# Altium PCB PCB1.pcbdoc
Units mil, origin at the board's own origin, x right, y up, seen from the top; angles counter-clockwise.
Board outline 2204.33 x 2174.33 mil, 4 copper layers (Top Layer, Inner1, Inner2, Bottom Layer); 61 components, 57 nets, 255 pads, 99 vias.
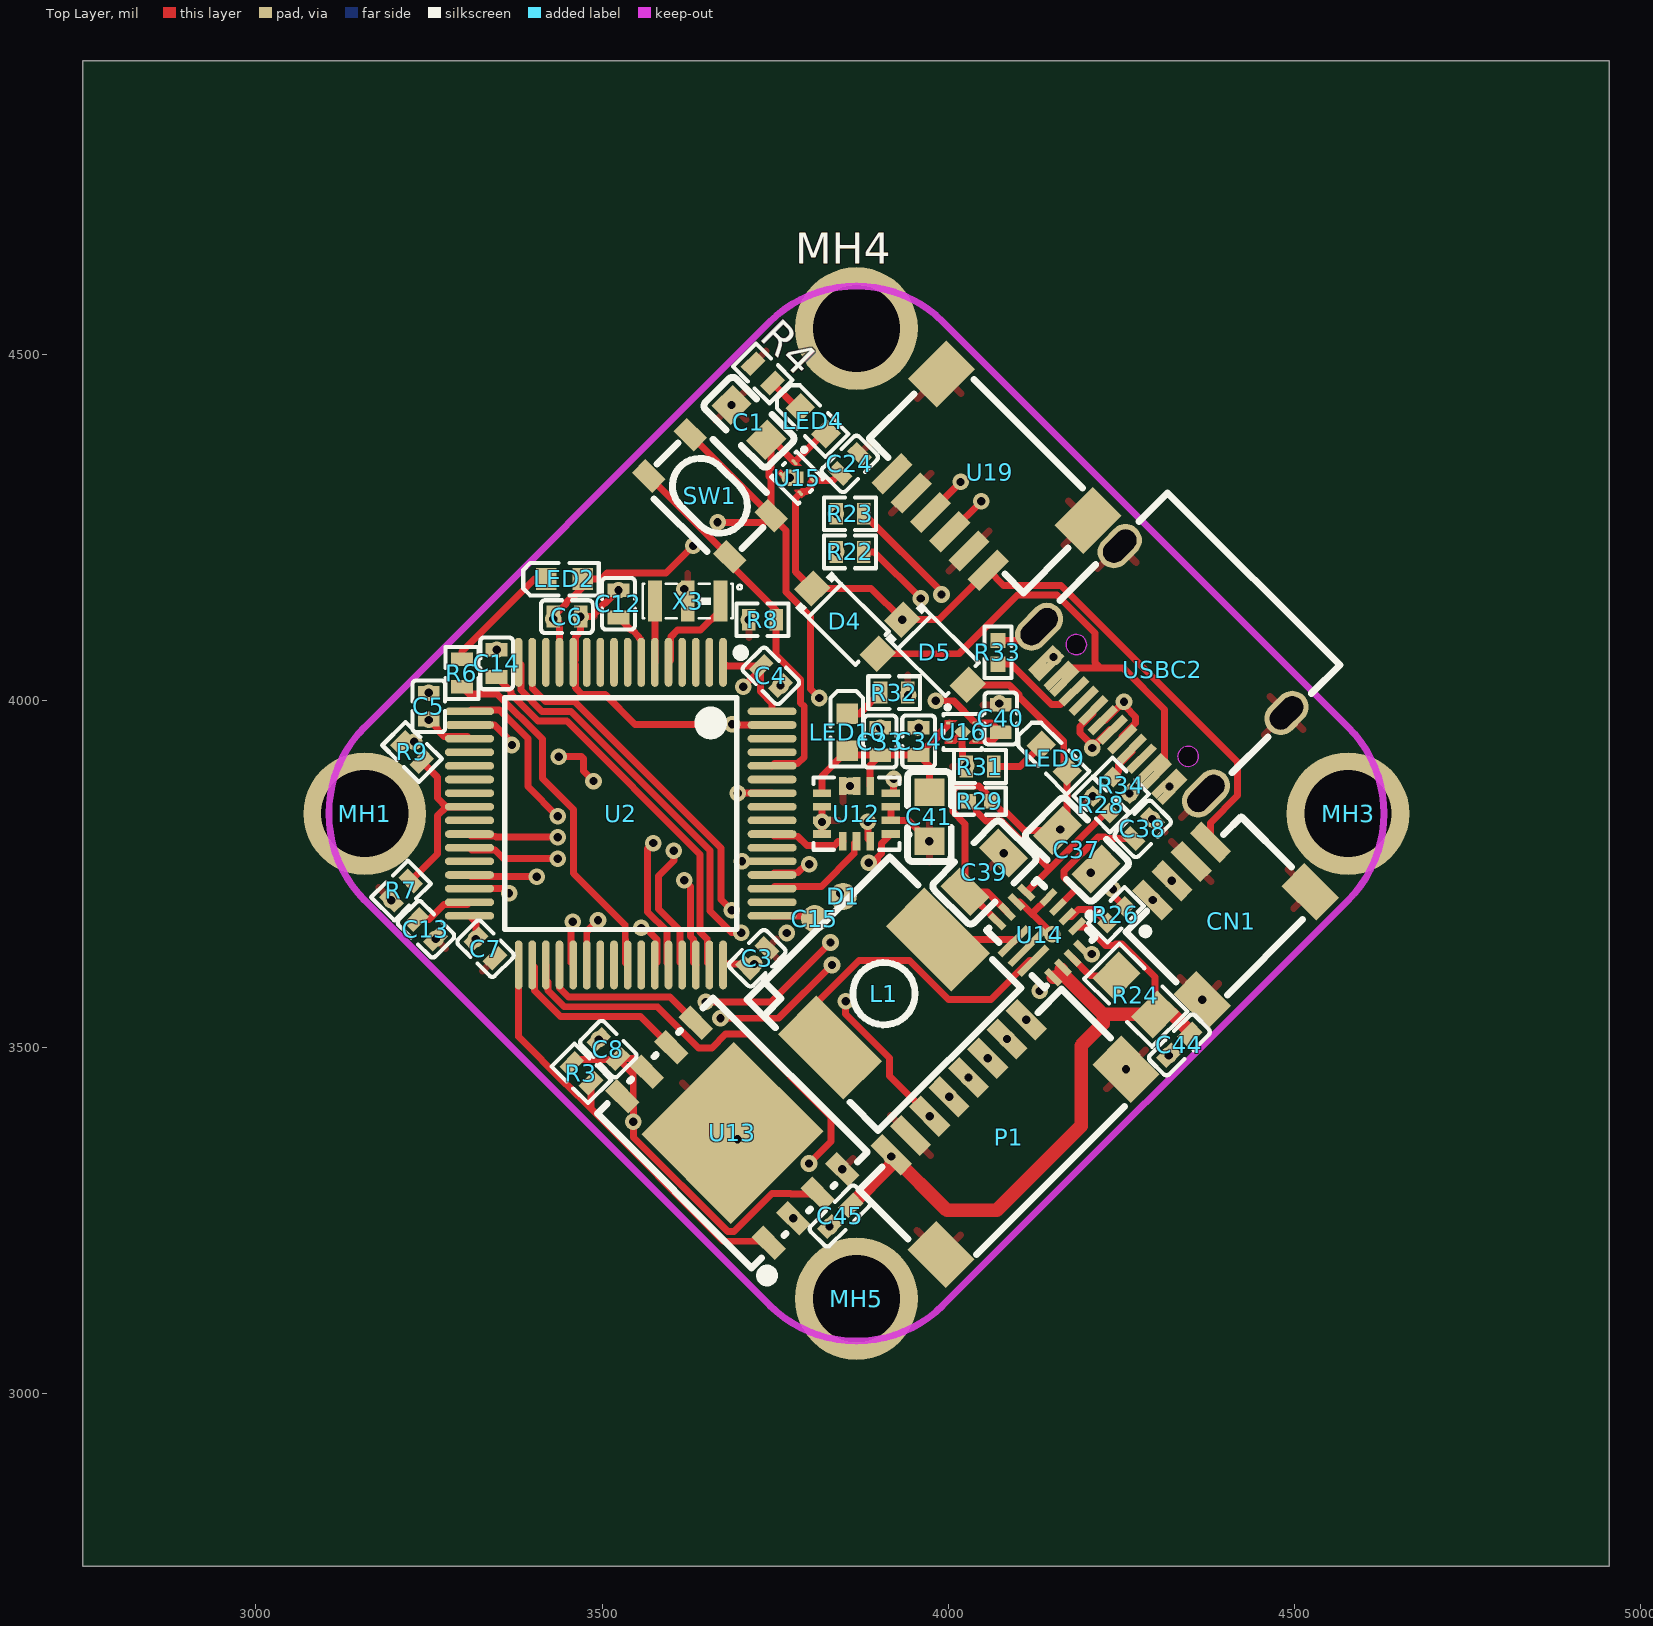
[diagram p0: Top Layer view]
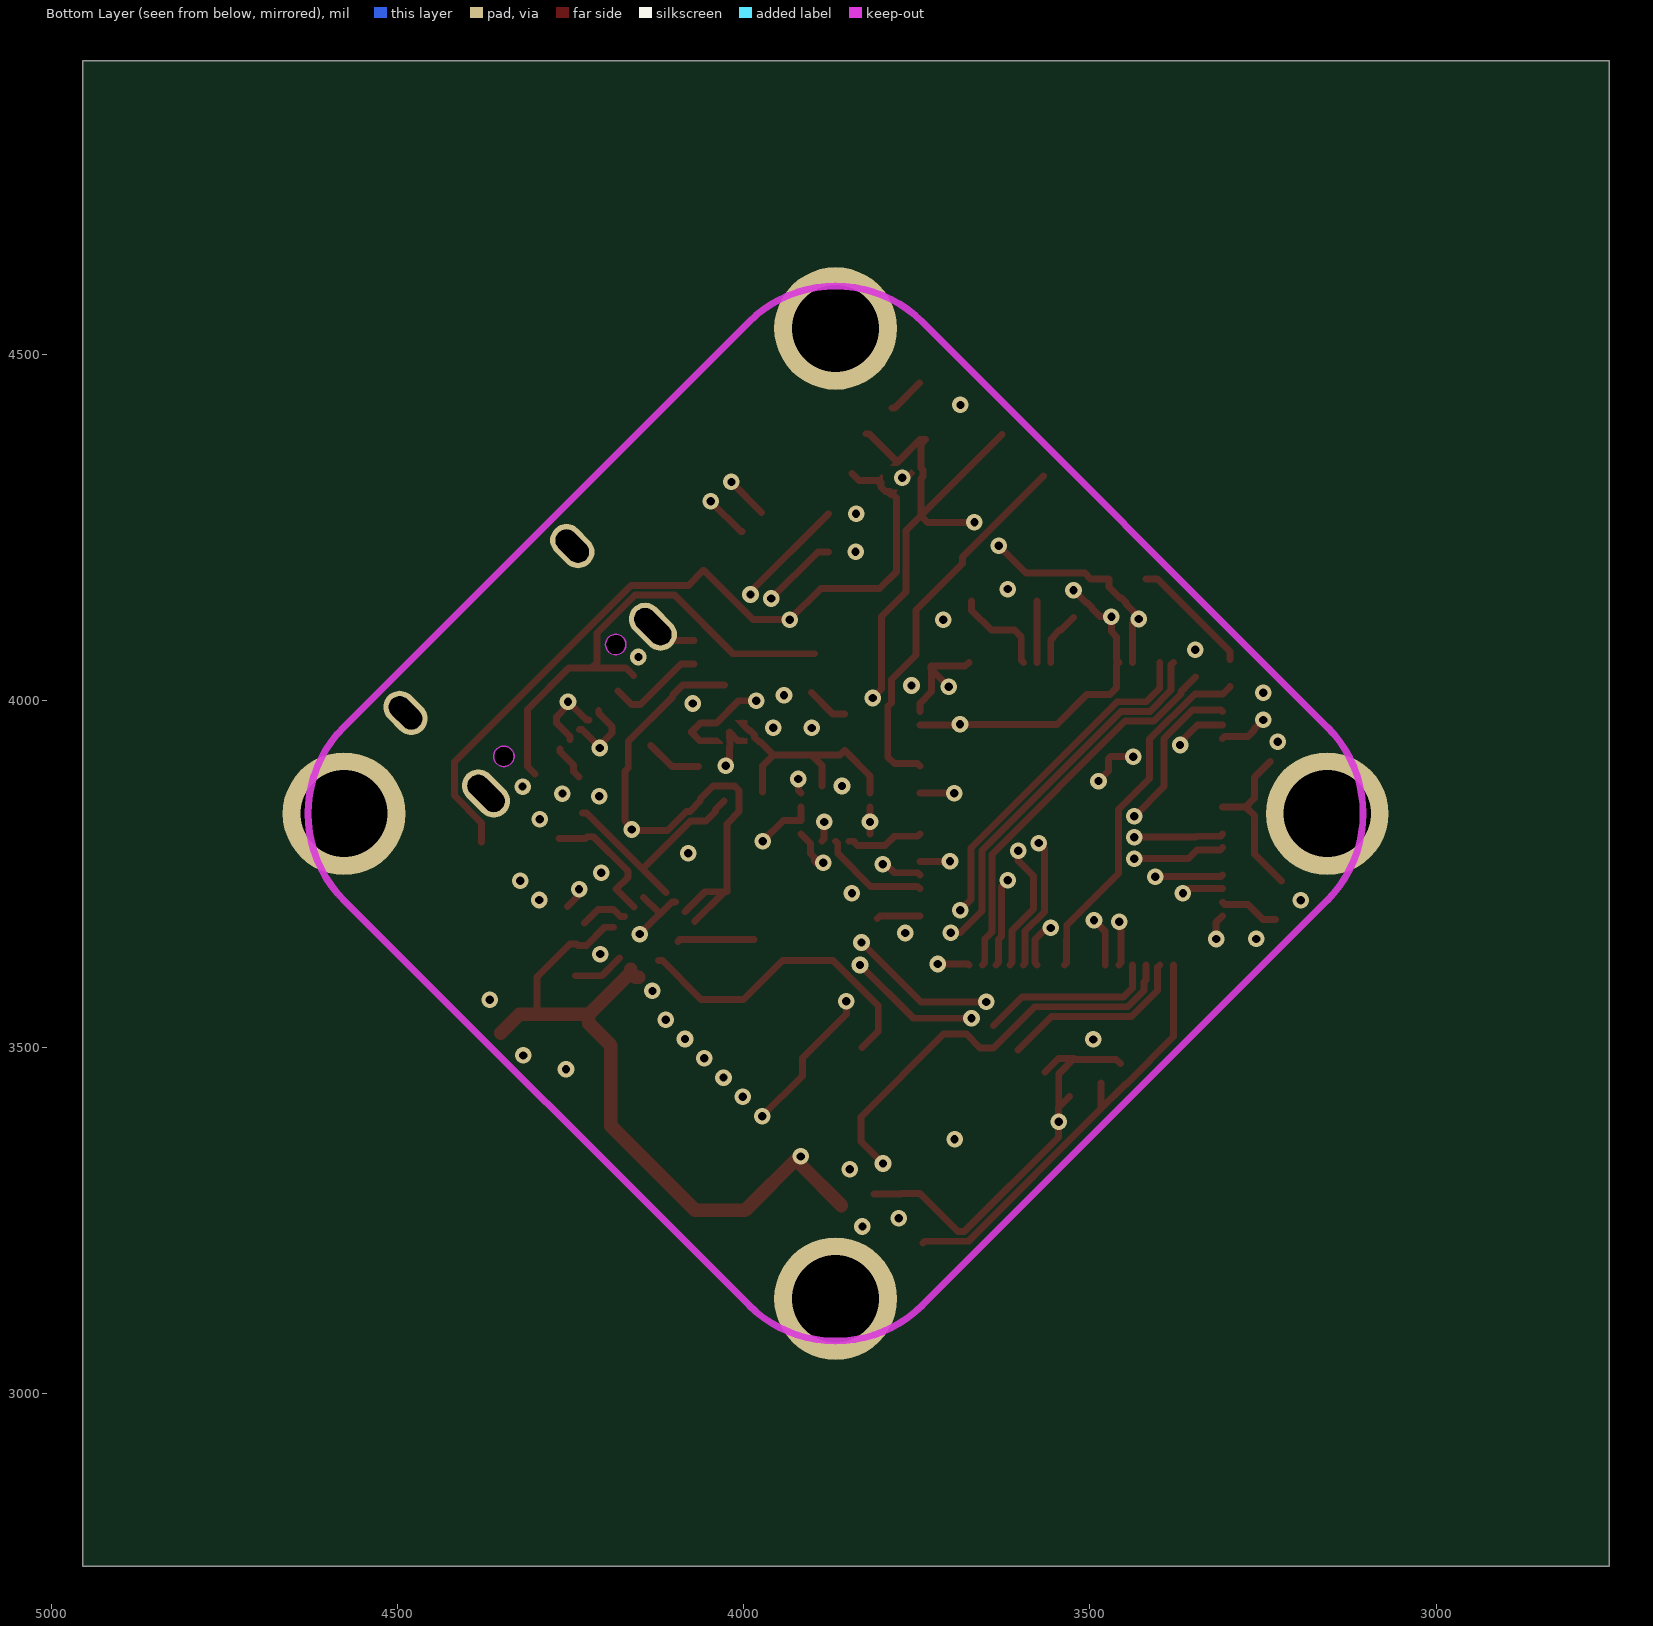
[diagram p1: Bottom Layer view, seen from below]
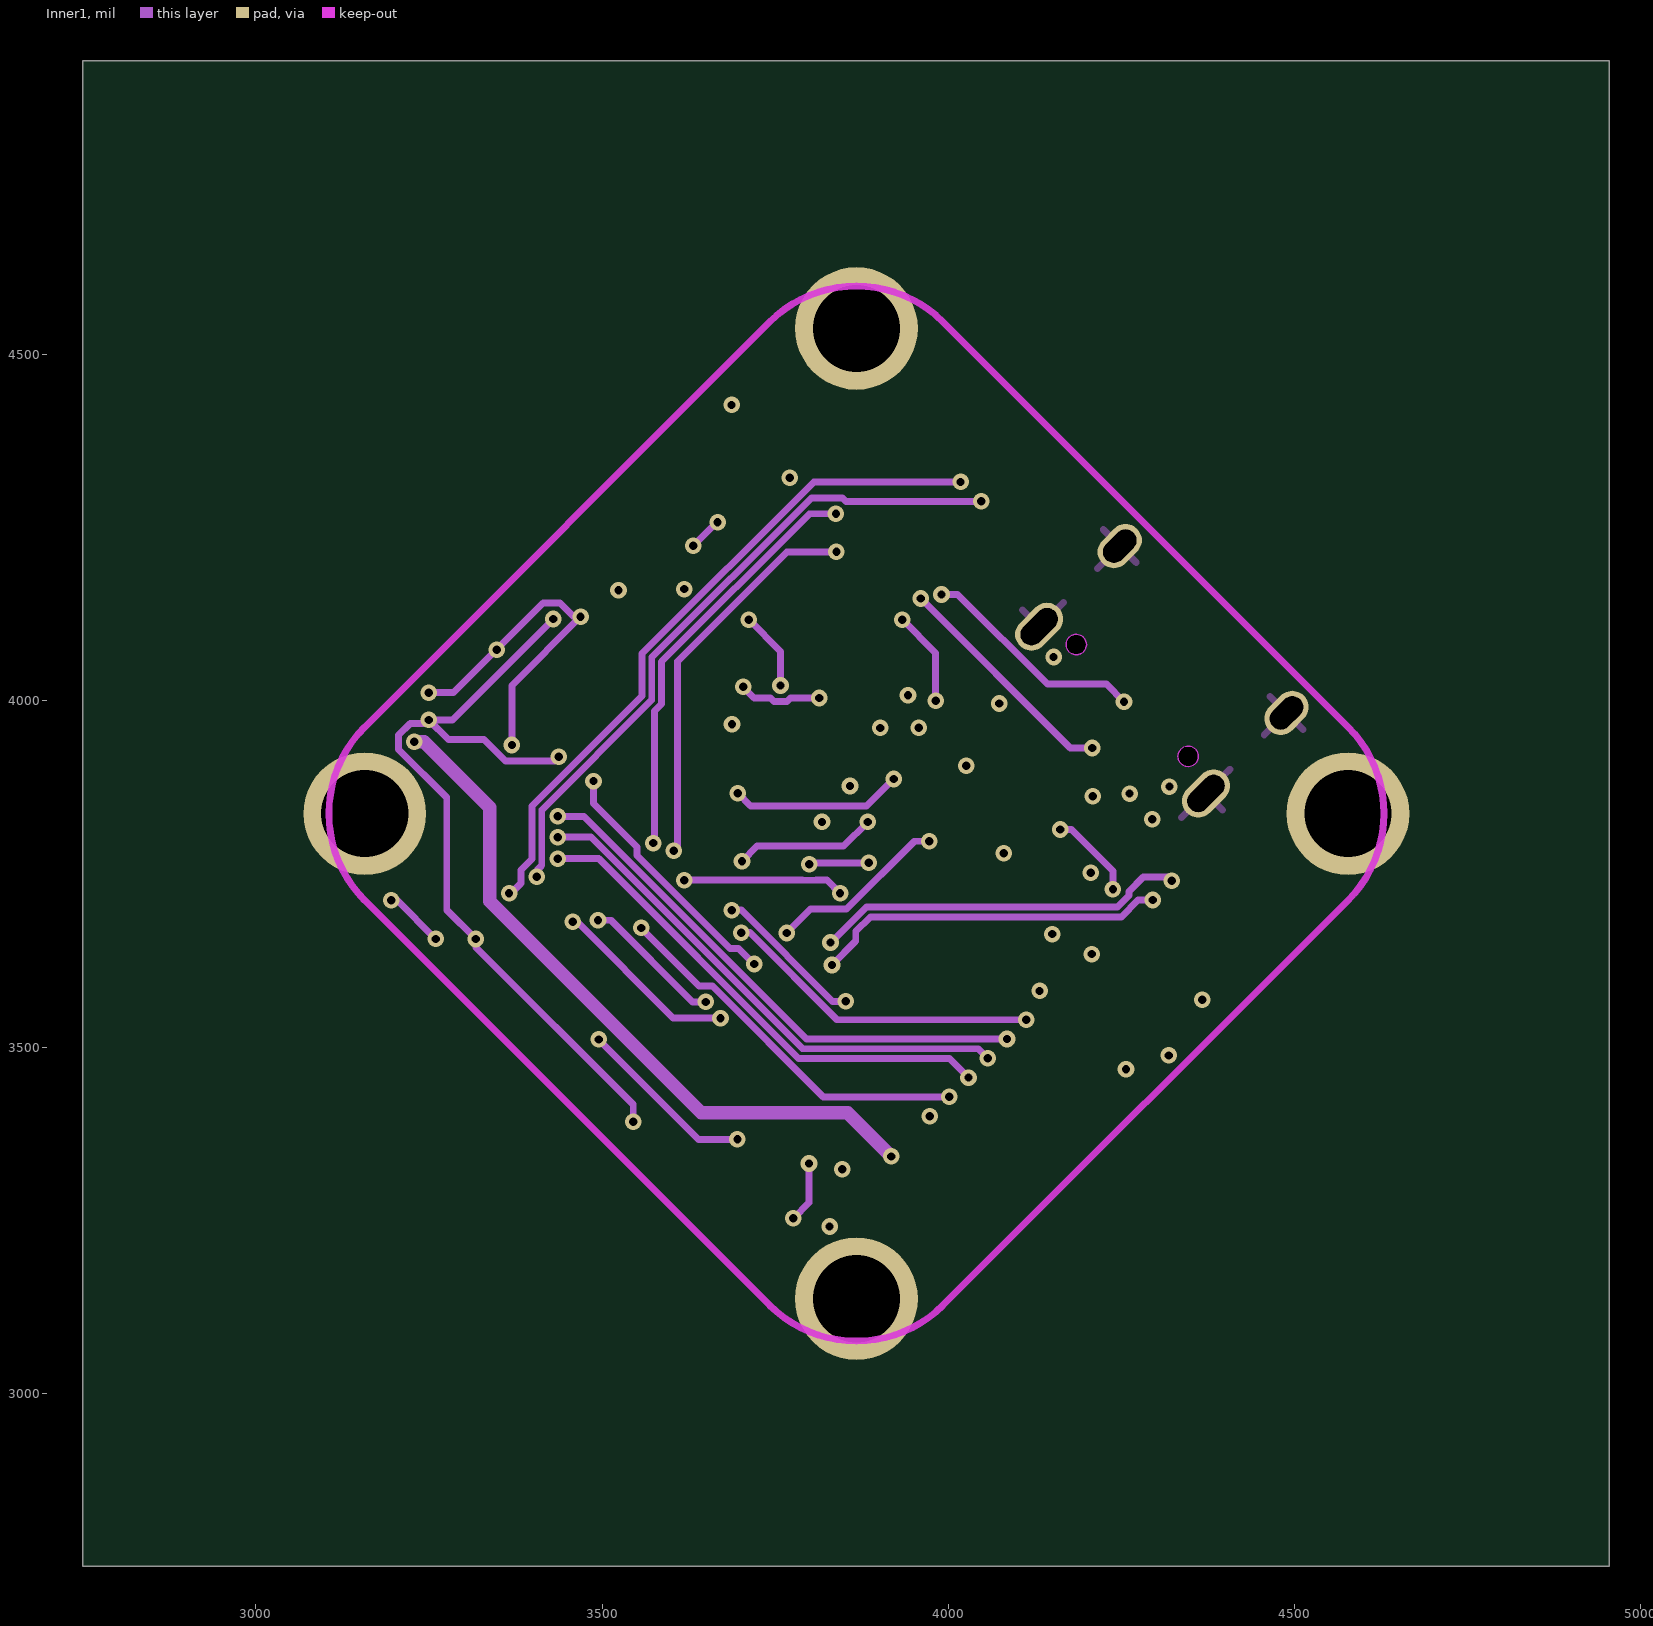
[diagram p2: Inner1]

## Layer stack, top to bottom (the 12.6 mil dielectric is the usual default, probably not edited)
Top Layer: signal copper (thickness not stored)
Dielectric: dielectric 12.6, FR-4, Dk 4.8
Inner1: signal copper (thickness not stored)
Dielectric: dielectric 12.6, FR-4, Dk 4.8
Inner2: signal copper (thickness not stored)
Dielectric: dielectric 12.6, FR-4, Dk 4.8
Bottom Layer: signal copper (thickness not stored)

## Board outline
4954.33,2750 2750,2750 2750,4924.33 4954.33,4924.33

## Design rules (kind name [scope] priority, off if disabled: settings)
BoardOutlineClearance copperThickness1oz [All] p0: genericclearance=10 ignorepadtopadclearanceinfootprint=FALSE except(0: Arc-SplitContinuation Track-SplitContinuation SMDPad-SplitContinuation THPad-SplitContinuation Via-SplitContinuation Fill-SplitContinuation Poly-SplitContinuation Region-SplitContinuation Text-SplitContinuation; 6: Track-CutoutEdge SMDPad-CutoutEdge THPad-CutoutEdge Via-CutoutEdge Region-CutoutEdge; 11.8: Track-OutlineEdge SMDPad-OutlineEdge THPad-OutlineEdge Via-OutlineEdge Fill-OutlineEdge Region-OutlineEdge Poly-OutlineEdge Text-OutlineEdge Fill-CutoutEdge)
BoardOutlineClearance copperThickness2oz [All] p0: genericclearance=10 ignorepadtopadclearanceinfootprint=FALSE except(0: Arc-SplitContinuation Track-SplitContinuation SMDPad-SplitContinuation THPad-SplitContinuation Via-SplitContinuation Fill-SplitContinuation Poly-SplitContinuation Region-SplitContinuation Text-SplitContinuation; 6: Track-CutoutEdge SMDPad-CutoutEdge THPad-CutoutEdge Via-CutoutEdge Region-CutoutEdge; 11.8: Track-OutlineEdge SMDPad-OutlineEdge THPad-OutlineEdge Via-OutlineEdge Fill-OutlineEdge Region-OutlineEdge Poly-OutlineEdge Text-OutlineEdge Fill-CutoutEdge)
Clearance copperThickness1oz [(InNet('GND') OR InNet('3V3') OR InNet('$1N1828') OR InNet('$1N1826') OR InNet('$1N1817') OR InNet('$1N1793') OR InNet('5V') OR InNet('5V_REG') OR InNet('3V3_MPU') OR InNet('$1N6590') OR InNet('RX6') OR InNet('TX6') OR InNet('$1N1792') OR InNet('5V_USB') OR InNet('$1N5670') OR InNet('$1N5674') OR InNet('$1N1796') OR InNet('$1N3338') OR InNet('$1N6799') OR InNet('$1N9049') OR InNet('ADC_CURR') OR InNet('RX1') OR InNet('MOTOR_1') OR InNet('MOTOR_2') OR InNet('MOTOR_3') OR InNet('MOTOR_4') OR InNet('SPI_CS_2') OR InNet('$1N1788') OR InNet('$1N1794') OR InNet('$1N1825') OR InNet('$1N4900') OR InNet('$1N5005') OR InNet('USB_D+_PA12') OR InNet('USB_DP') OR InNet('USB_D-_PA11') OR InNet('USB_DN') OR InNet('$1N5764') OR InNet('$1N6103') OR InNet('$1N6255') OR InNet('GYRO_EXTI') OR InNet('SPI_CS_3') OR InNet('SPI_MOSI_3') OR InNet('SPI_MISO_3') OR InNet('SPI_SCK_3') OR InNet('TX1') OR InNet('SPI_MOSI_2') OR InNet('SPI_MISO_2') OR InNet('SPI_SCK_2') OR InNet('RX3') OR InNet('TX3') OR InNet('SPI_MOSI_1') OR InNet('SPI_MISO_1') OR InNet('SPI_SCK_1') OR InNet('SPI_CS_1') OR InNet('$1N1822') OR InNet('$1N1808'))] p1: gap=7 ignorepadtopadclearanceinfootprint=FALSE except(4: Track-Track; 6: Track-SMDPad SMDPad-SMDPad Track-THPad SMDPad-THPad THPad-THPad Track-Via SMDPad-Via THPad-Via Via-Via SMDPad-Fill THPad-Fill Via-Fill Fill-Fill Track-Region SMDPad-Region THPad-Region Via-Region Region-Region Track-Poly SMDPad-Poly THPad-Poly Via-Poly Fill-Poly Region-Poly Poly-Poly Track-Text SMDPad-Text THPad-Text Via-Text Fill-Text Region-Text Poly-Text Text-Text; 6.9: Track-Hole SMDPad-Hole THPad-Hole Via-Hole Fill-Hole Region-Hole Poly-Hole Text-Hole Sheet-Hole; 11.8: Track-Fill Fill-Region Track-Sheet SMDPad-Sheet THPad-Sheet Via-Sheet Fill-Sheet Region-Sheet Poly-Sheet Text-Sheet)
Clearance copperThickness2oz [(InNet('VBAT'))] p1: gap=7 ignorepadtopadclearanceinfootprint=FALSE except(6: Track-SMDPad SMDPad-SMDPad Track-THPad SMDPad-THPad THPad-THPad Track-Via SMDPad-Via THPad-Via Via-Via SMDPad-Fill THPad-Fill Via-Fill Fill-Fill Track-Region SMDPad-Region THPad-Region Via-Region Region-Region Track-Poly SMDPad-Poly THPad-Poly Via-Poly Fill-Poly Region-Poly Poly-Poly Track-Text SMDPad-Text THPad-Text Via-Text Fill-Text Region-Text Poly-Text Text-Text; 6.9: Track-Hole SMDPad-Hole THPad-Hole Via-Hole Fill-Hole Region-Hole Poly-Hole Text-Hole Sheet-Hole; 8: Track-Track; 11.8: Track-Fill Fill-Region Track-Sheet SMDPad-Sheet THPad-Sheet Via-Sheet Fill-Sheet Region-Sheet Poly-Sheet Text-Sheet)
DiffPairsRouting differentialPair [All] p1: maxuncoupledlength=10 minlimit=5.9843 maxlimit=5.9843 mostfreqgap=5.9843 toplayer_minwidth=5 toplayer_prefwidth=10 toplayer_maxwidth=100 bottomlayer_minwidth=5 bottomlayer_prefwidth=10 bottomlayer_maxwidth=100 midlayer1_minwidth=5 midlayer1_prefwidth=10 midlayer1_maxwidth=100 midlayer2_minwidth=5 midlayer2_prefwidth=10 midlayer2_maxwidth=100
PasteMaskExpansion pasteMaskExpansion [All] p1: expansion=0
PlaneConnect innerPlane [All] p1: planeconnectstyle=Relief reliefexpansion=20 reliefentries=4 reliefconductorwidth=10 reliefairgap=10
PolygonConnect copperRegion [All] p1: connectstyle=Relief reliefentries=4 reliefconductorwidth=10 polygonreliefangle="90 Angle" airgapwidth=10
RoutingVias viaSize [All] p1: viastyle="Through Hole" holewidth=12.0078 minholewidth=11.811 maxholewidth=248.0314 width=24.0158 minwidth=19.685 maxwidth=393.7008
SolderMaskExpansion solderMaskExpansion [All] p1: useseparateexpansions=TRUE expansion=2.0079 expansionbottom=2.0079
Width copperThickness1oz [All] p1: maxlimit=100 minlimit=5 preferedwidth=10
Width copperThickness2oz [All] p1: maxlimit=39 minlimit=4 preferedwidth=20

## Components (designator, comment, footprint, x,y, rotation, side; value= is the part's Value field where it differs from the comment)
C1 "2.2uF" C0603 3711.99,4402.29 r315 top
C3 "100nF" C0402#1 3723.99,3628.37 r45 top
C4 "100nF" C0402#1 3743.63,4036.14 r315 top
C5 "100nF" C0402#1 3249.63,3992.14 r90 top
C6 "100nF" C0402#1 3449.18,4121.6 r0 top
C7 "100nF" C0402#1 3331.63,3642.14 r315 top
C8 "100nF" C0402#1 3509,3497.16 r315 top
C12 "100nF" C0402#1 3523.63,4140.14 r270 top
C13 "2.2uF" C0402#1 3245.63,3670.14 r315 top
C14 "2.2uF" C0402#1 3347.63,4054.14 r90 top
C15 "" "TEST PAD" 3807.01,3685.46 r0 top
C24 "1uF" C0402#1 3857.63,4342.14 r225 top
C33 "100nF" C0402#1 3901.68,3941.22 r270 top
C34 "100nF" C0402#1 3957,3941.52 r90 top
C37 "47uF" C0805 4185.63,3785.14 r135 top
C38 "100nF" C0402#1 4280.63,3815.14 r45 top
C39 "47uF" C0805 4052,3752.16 r225 top
C40 "1uF" C0402#1 4075.63,3974.52 r270 top
C41 "2.2uF" C0603 3972.6,3832.71 r90 top
C44 "" C0402#2 4333.63,3503.14 r225 top
C45 "" C0402#2 3843.63,3256.14 r225 top
CN1 "" CONN-SMD_4P-P1.00_SM04B-SRSS-TB-LF-SN 4390.63,3700.14 r45 top
D1 "" "TEST PAD" 3848.01,3717.52 r0 top
D4 "" SOD-123_L2.6-W1.7-LS3.5-RD 3850.63,4115.14 r315 top
D5 "" SOD-123_L2.6-W1.7-LS3.5-RD 3980.63,4070.14 r315 top
L1 "" IND-SMD_L7.1-W6.5-P5.60 3907,3577.16 r45 top
LED2 "" LED0402-R-RD 3445.63,4176.14 r0 top
LED4 "" LED0402-R-RD 3804.62,4404.41 r315 top
LED9 "" LED0402-R-RD 4152.82,3917.07 r315 top
LED10 "" LED0402-R-RD 3853.97,3954.64 r270 top
MH1 "" MHOLE-3MM-simple 3157.39,3837.16 r0 top
MH3 "" MHOLE-3MM-simple 4577.08,3837.16 r0 top
MH4 "" MHOLE-3MM-simple 3867.24,4537.75 r0 top
MH5 "" MHOLE-3MM-simple 3867.24,3136.57 r0 top
P1 "" CONN-TH_SM08B-SRSS-TB-LF-SN 4069,3388.16 r45 top
R3 "10K" R0402#1 3470,3462.16 r135 top
R4 "1K" R0402#1 3731.99,4472.92 r315 top
R6 "1K" R0402#1 3297.63,4040.14 r90 top
R7 "1K" R0402#1 3209.63,3726.14 r45 top
R8 "10K" R0402#1 3731.64,4117.16 r0 top
R9 "10K" R0402#1 3225.63,3926.14 r135 top
R22 "22" R0402#1 3858.01,4215.16 r180 top
R23 "22" R0402#1 3858.01,4270.16 r180 top
R24 "" R0805 4270.63,3575.14 r315 top
R26 "" R0402#2 4242,3691.26 r225 top
R28 "" R0402#2 4220.63,3850.14 r315 top
R29 "" R0402#2 4045.63,3855.14 r180 top
R31 "1K" R0402#1 4045.63,3905.14 r0 top
R32 "1K" R0402#1 3921.68,4011.85 r180 top
R33 "" R0402#2 4071.63,4070.14 r270 top
R34 "" R0402#2 4249.63,3878.14 r315 top
SW1 "" KEY-SMD_4P-L4.2-W3.2-P2.20-LS4.6 3655.63,4296.14 r135 top
U2 "" LQFP-64_L10.0-W10.0-P0.50-LS12.0-BL 3527,3837.16 r180 top
U12 "" LGA-14_L3.0-W2.5-P0.50-TL 3867.24,3837.16 r180 top
U13 "" WSON-8_L8.0-W6.0-P1.27-BL-EP 3688.02,3376.15 r45 top
U14 "" VQFN-HR-15_L3.0-W2.5-P0.50-BL_TPS63070RNMR 4137,3667.16 r135 top
U15 "" XDFN-4_L1.0-W1.0-P0.65-BL-EP 3781.99,4322.29 r225 top
U16 "" XDFN-4_L1.0-W1.0-P0.65-BL-EP 4020.63,3955.14 r270 top
U19 "" CONN-SMD_SM06B-SRSS-TB-LF-SN 4042,4312.16 r135 top
USBC2 "" USB-C_SMD-TYPE-C-31-M-12 4299,4034.16 r135 top
X3 "" OSC-SMD_3P-L3.2-W1.3-P1.20 3623.63,4144.14 r180 top

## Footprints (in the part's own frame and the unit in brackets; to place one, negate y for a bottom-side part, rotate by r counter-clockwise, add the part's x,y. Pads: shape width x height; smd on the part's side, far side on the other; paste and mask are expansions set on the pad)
C0402#1 [mm]
  rect 0.5x0.8 smd: 1(-0.5,0) 2(0.5,0)
  silkscreen extent -0.95,-0.6 0.95,0.6
C0402#2 [mm]
  rect 0.79x0.54 smd: 1(-0.545,0) 2(0.545,0)
  silkscreen extent -1.17,-0.5 1.17,0.5
C0603 [mm]
  rect 1x1.1 smd: 1(-0.9,0) 2(0.9,0)
  silkscreen extent -1.65,-0.8 1.65,0.8
C0805 [mm]
  rect 1x1.55 smd: 1(-1,0) 2(1,0)
  silkscreen extent -1.75,-1.04 1.75,1.04
CONN-SMD_4P-P1.00_SM04B-SRSS-TB-LF-SN [mm]
  rect 0.6x1.55 smd: 1(-1.5,1.938) 2(-0.5,1.938) 3(0.5,1.938) 4(1.5,1.938)
  rect 1.2x1.8 smd: 5(2.8,-1.938) 6(-2.8,-1.938)
  silkscreen extent -3.02,-2.46 2.96,1.8
CONN-SMD_SM06B-SRSS-TB-LF-SN [mm]
  rect 0.6x1.55 smd: 1(-2.5,1.938) 2(-1.5,1.938) 3(-0.5,1.938) 4(0.5,1.938) 5(1.5,1.938) 6(2.5,1.938)
  rect 1.5x2 smd: 7(3.8,-1.938) 8(-3.8,-1.938)
  silkscreen extent -4,-2.64 4,1.61
CONN-TH_SM08B-SRSS-TB-LF-SN [mm]
  rect 0.6x1.55 smd: 1(-3.5,1.937) 2(-2.502,1.938) 3(-1.502,1.938) 4(-0.502,1.938) 5(0.5,1.937) 6(1.498,1.938) 7(2.498,1.938) 8(3.5,1.937)
  rect 1.5x2 smd: 9(4.8,-1.938) 10(-4.8,-1.938)
  silkscreen extent -5.26,-2.86 5.22,1.86
IND-SMD_L7.1-W6.5-P5.60 [mm]
  rect 2x3.4 smd: 1(-2.8,0) 2(2.8,0)
  silkscreen extent -3.7,-3.4 3.7,3.4
KEY-SMD_4P-L4.2-W3.2-P2.20-LS4.6 [mm]
  rect 1.05x0.7 smd: 1(-2.1,1.075) 2(2.1,1.075) 3(-2.1,-1.075) 4(2.1,-1.075)
  silkscreen extent -2.2,-1.55 2.2,1.52
LED0402-R-RD [mil]
  rect 29.53x31.5 smd: 1(26.5,0) 2(-26.5,0)
  silkscreen extent -60,-24 50,23
LGA-14_L3.0-W2.5-P0.50-TL [mm]
  rect 0.675x0.28 smd: 1(-1.262,0.75) 2(-1.262,0.25) 3(-1.262,-0.25) 4(-1.262,-0.75) 8(1.262,-0.75) 9(1.262,-0.25) 10(1.262,0.25) 11(1.262,0.75)
  rect 0.28x0.675 smd: 5(-0.5,-1.012) 6(0,-1.012) 7(0.5,-1.012) 12(0.5,1.012) 13(0,1.012) 14(-0.5,1.012)
  silkscreen extent -1.98,-1.33 1.58,1.33
LQFP-64_L10.0-W10.0-P0.50-LS12.0-BL [mm]
  oval 0.28x1.8 smd: 1(-3.75,-5.55) 2(-3.25,-5.55) 3(-2.75,-5.55) 4(-2.25,-5.55) 5(-1.75,-5.55) 6(-1.25,-5.55) 7(-0.75,-5.55) 8(-0.25,-5.55) 9(0.25,-5.55) 10(0.75,-5.55) 11(1.25,-5.55) 12(1.75,-5.55) 13(2.25,-5.55) 14(2.75,-5.55) 15(3.25,-5.55) 16(3.75,-5.55) 33(3.75,5.55) 34(3.25,5.55) 35(2.75,5.55) 36(2.25,5.55) 37(1.75,5.55) 38(1.25,5.55) 39(0.75,5.55) 40(0.25,5.55) 41(-0.25,5.55) 42(-0.75,5.55) 43(-1.25,5.55) 44(-1.75,5.55) 45(-2.25,5.55) 46(-2.75,5.55) 47(-3.25,5.55) 48(-3.75,5.55)
  oval 1.8x0.28 smd: 17(5.55,-3.75) 18(5.55,-3.25) 19(5.55,-2.75) 20(5.55,-2.25) 21(5.55,-1.75) 22(5.55,-1.25) 23(5.55,-0.75) 24(5.55,-0.25) 25(5.55,0.25) 26(5.55,0.75) 27(5.55,1.25) 28(5.55,1.75) 29(5.55,2.25) 30(5.55,2.75) 31(5.55,3.25) 32(5.55,3.75) 49(-5.55,3.75) 50(-5.55,3.25) 51(-5.55,2.75) 52(-5.55,2.25) 53(-5.55,1.75) 54(-5.55,1.25) 55(-5.55,0.75) 56(-5.55,0.25) 57(-5.55,-0.25) 58(-5.55,-0.75) 59(-5.55,-1.25) 60(-5.55,-1.75) 61(-5.55,-2.25) 62(-5.55,-2.75) 63(-5.55,-3.25) 64(-5.55,-3.75)
  silkscreen extent -4.55,-6.05 4.25,4.25
MHOLE-3MM-simple [mm]
  round 4.5 hole 3.2: 1(0,0)
OSC-SMD_3P-L3.2-W1.3-P1.20 [mm]
  rect 0.5x1.5 smd: 1(-1.2,0) 2(0,0) 3(1.2,0)
  silkscreen extent -1.99,-0.64 1.65,0.64
R0402#1 [mm]
  rect 0.5x0.8 smd: 1(-0.5,0) 2(0.5,0)
  silkscreen extent -0.95,-0.6 0.95,0.6
R0402#2 [mm]
  rect 0.566x0.54 smd: 1(-0.433,0) 2(0.433,0)
  silkscreen extent -0.94,-0.5 0.94,0.5
R0805 [mm]
  rect 1.133x1.377 smd: 1(-1,0) 2(1,0)
  silkscreen extent -1.76,-0.92 1.76,0.92
SOD-123_L2.6-W1.7-LS3.5-RD [mm]
  rect 0.9x1 smd: 1(-1.692,0) 2(1.692,0)
  silkscreen extent -1.63,-0.94 1.41,0.94
"TEST PAD" [mm]
  round 1 smd: 1(0,0)
USB-C_SMD-TYPE-C-31-M-12 [mm]
  oval 1.2x2 hole 0.8 slot 1.6 at 90 deg: 0(-4.325,1.706) 1(4.325,1.706)
  oval 1.2x1.8 hole 0.8 slot 1.4 at 90 deg: 2(4.325,-2.474) 3(-4.325,-2.474)
  rect 0.3x1.3 smd: A1(-3.35,2.474) A4(-2.55,2.474) A5(-1.25,2.474) A6(-0.25,2.474) A7(0.25,2.474) A8(1.25,2.474) A9(2.55,2.474) A12(3.35,2.474) B1(3.05,2.474) B4(2.25,2.474) B5(1.75,2.474) B6(0.75,2.474) B7(-0.75,2.474) B8(-1.75,2.474) B9(-2.25,2.474) B12(-3.05,2.474)
  Board Outline Layer circle w0.005: c-2.9,1.206 r0.375
  Board Outline Layer circle w0.005: c2.9,1.206 r0.375
  Board Outline Layer region: -3.165,0.94 -3.254,1.082 -3.273,1.248 -3.217,1.405 -3.099,1.523 -2.942,1.578 -2.776,1.56 -2.635,1.471 -2.635,1.471 -2.546,1.33 -2.527,1.164 -2.582,1.006 -2.7,0.888 -2.858,0.833 -3.024,0.852 -3.165,0.94
  Board Outline Layer region: 2.635,0.94 2.546,1.082 2.527,1.248 2.582,1.405 2.7,1.523 2.858,1.578 3.024,1.56 3.165,1.471 3.165,1.471 3.254,1.33 3.273,1.164 3.217,1.006 3.099,0.888 2.942,0.833 2.776,0.852 2.635,0.94
  Multi-Layer board cut-out: -3.165,0.94 -3.254,1.082 -3.273,1.248 -3.217,1.405 -3.099,1.523 -2.942,1.578 -2.776,1.56 -2.635,1.471 -2.635,1.471 -2.546,1.33 -2.527,1.164 -2.582,1.006 -2.7,0.888 -2.858,0.833 -3.024,0.852 -3.165,0.94
  Multi-Layer board cut-out: 2.635,0.94 2.546,1.082 2.527,1.248 2.582,1.405 2.7,1.523 2.858,1.578 3.024,1.56 3.165,1.471 3.165,1.471 3.254,1.33 3.273,1.164 3.217,1.006 3.099,0.888 2.942,0.833 2.776,0.852 2.635,0.94
  silkscreen extent -4.47,-5.09 4.47,0.49
VQFN-HR-15_L3.0-W2.5-P0.50-BL_TPS63070RNMR [mm]
  rect 0.25x0.7 smd: 1(-0.75,-1.016) 2(-0.25,-1.016) 3(0.25,-1.016) 4(0.75,-1.016)
  rect 0.7x0.25 smd: 5(1.45,-0.566) 6(1.45,-0.066) 7(1.45,0.434) 8(1.45,0.934) 12(-1.45,0.934) 13(-1.45,0.434) 14(-1.45,-0.066) 15(-1.45,-0.566)
  rect 0.25x1.45 smd: 9(0.5,1.016) 11(-0.5,1.016)
  rect 0.25x1.85 smd: 10(0,0.816)
  silkscreen extent -1.5,-1.73 1.5,1.44
WSON-8_L8.0-W6.0-P1.27-BL-EP [mm]
  rect 0.6x1.2 smd: 1(-1.905,-3.8) 2(-0.635,-3.8) 3(0.635,-3.8) 4(1.905,-3.8) 5(1.905,3.8) 6(0.635,3.8) 7(-0.635,3.8) 8(-1.905,3.8)
  rect 4.8x4.65 smd: 9(0,0)
  silkscreen extent -3,-4.8 3,4
XDFN-4_L1.0-W1.0-P0.65-BL-EP [mm]
  oval 0.12x0.27 smd: 1(-0.325,-0.475)
  oval 0.12x0.24 smd: 2(0.325,-0.475) 3(0.325,0.475) 4(-0.325,0.475)
  rect 0.45x0.45 smd rot 45: 5(0,0)
  Top Layer region: 0.425,-0.65 0.225,-0.65 0.225,-0.4 0.375,-0.25 0.425,-0.25
  Top Layer region: -0.425,0.65 -0.225,0.65 -0.225,0.4 -0.375,0.25 -0.425,0.25
  Top Layer region: 0.425,0.65 0.225,0.65 0.225,0.4 0.375,0.25 0.425,0.25
  Top Layer region: -0.225,-0.4 -0.225,-0.65 -0.425,-0.65 -0.425,-0.2 -0.375,-0.25
  silkscreen extent -0.98,-0.7 0.66,0.7

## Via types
v1: diameter 24.02, hole 12.01, Top Layer to Bottom Layer, 99 vias

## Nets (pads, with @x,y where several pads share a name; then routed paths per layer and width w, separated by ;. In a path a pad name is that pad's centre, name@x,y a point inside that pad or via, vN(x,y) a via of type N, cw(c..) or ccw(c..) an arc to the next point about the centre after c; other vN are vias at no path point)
3V3: C1.2 C3.1 C4.1 C5.1 C6.1 C7.1 C8.2 LED2.1 LED4.1 R3.2 SW1.3 SW1.4 U2.1 U2.13 U2.19 U2.32 U2.48 U2.64 U13.3 U13.7 U13.8 U15.1 | length 3862.7
  Top Layer w10: v1(3249.63,3972.46) 3262.08,3960.01 3262.08,3958.29 3271.74,3948.62 3305.31,3948.62 U2.19 ; U2.32 3317.71,3680.31 v1(3317.71,3656.06) ; v1(3437.35,3919.48) 3470.29,3919.48 3472.86,3916.91 3472.86,3898.91 v1(3487.63,3884.14) ; U2.13 3438.42,4112.69 C6.1 3448.05,4140.14 3448.05,4141.89 3454.48,4148.33 3456.24,4148.33 3472.13,4164.22 LED2.1 3498.83,4176.14 3507.34,4184.65 3592.14,4184.65 v1(3631.63,4224.14) ; R3.2 3462,3482 3521.68,3482 C8.2 ; U13.8 U13.8@3544.92,3413.18 ; v1(3544.92,3392.12) U13.8@3544.92,3413.18 ; U13.7 3545.57,3483.24 C8.2 ; SW1.4 SW1.3 ; v1(3666.71,4257.73) 3734.15,4257.73 SW1.3 ; U2.48 3675.88,3619.92 v1(3719.54,3619.92) ; U2.1 3680.25,4050.06 C4.1 3729.71,4046.23 C4.1@3728.47,4044.99 ; v1(3703.63,4020.14) C4.1@3728.47,4044.99 ; U2.64 3745.5,3996.47 3728.47,4013.49 C4.1@3728.47,4044.99 ; U13.3 3773.01,3288.04 3772.33,3288.72 3745.56,3288.72 3690.48,3233.65 3681.38,3233.65 3545.49,3369.53 3545.49,3412.61 U13.8@3544.92,3413.18 ; v1(3813.63,4004.14) 3800.65,4017.12 3800.65,4121.75 3765.35,4157.05 3765.35,4246.28 SW1.3 ; LED4.1 3818.91,4385.67 U15.1 3745.15,4377.23 C1.2 3744.02,4370.26 3744.02,4336.06 3741.07,4333.11 3741.07,4324.01 3744.02,4321.06 SW1.3 ; C8.2 3544.92,3461.24 U13.8@3544.92,3413.18
  Inner1 w10: v1(3429.63,4118.14) 3283.95,3972.46 v1(3249.63,3972.46) ; v1(3437.35,3919.48) 3431.12,3913.25 3360.21,3913.25 3329.31,3944.14 3277.95,3944.14 v1(3249.63,3972.46) ; v1(3487.63,3884.14) 3487.63,3851.82 3550.66,3788.79 3550.66,3776.46 3684.84,3642.28 3697.17,3642.28 v1(3719.54,3619.92) ; v1(3544.92,3392.12) 3544.92,3416.85 3317.71,3644.06 v1(3317.71,3656.06) 3275.63,3698.14 3275.63,3860.14 3205.88,3929.9 3205.88,3950.42 3222.91,3967.46 3244.63,3967.46 v1(3249.63,3972.46) ; v1(3631.63,4224.14) 3665.22,4257.73 v1(3666.71,4257.73) ; v1(3703.63,4020.14) 3719.63,4004.14 3743.11,4004.14 3748.03,3999.23 3767.08,3999.23 3771.99,4004.14 v1(3813.63,4004.14)
3V3_MPU: C33.2 C34.1 C41.2 LED10.1 U12.5 U12.8 U16.1 | length 360.1
  Top Layer w10: U12.8 3817.55,3891.72 LED10.1 3860.58,3921.53 C33.2 ; U12.5 3886.92,3906.78 C33.2 ; C41.2 3972.61,3906.24 C34.1 ; U16.1 4001.92,3966.77 3992.42,3957.26 3990.48,3957.26 3984.05,3950.83 3984.05,3947.14 3977.3,3940.39 3975.54,3940.39 C34.1 ; C33.2 3956.69,3921.53 C34.1
5V: C24.2 C40.2 CN1.4 D4.1 D5.1 U15.3 U15.4 U16.3 U16.4 U19.1 | length 1424.2
  Top Layer w10: U15.3 3779.36,4293.22 3779.36,4186.41 D4.1 3888.52,4162.26 v1(3933.52,4117.26) 3986.29,4117.26 U19.1 4079.45,4166.84 4162.38,4166.84 4417.66,3911.56 4417.66,3863.07 4378.46,3823.87 CN1.4 ; U15.3 3788.61,4302.45 3795.4,4302.45 3801.83,4308.89 3801.83,4315.68 U15.4 3833.6,4318.11 C24.2 ; v1(3981.63,4000.14) 4007.26,4000.14 4039.34,3968.06 U16.4 4062.52,3967.94 C40.2 4063.14,3942.34 U16.3
  Inner1 w10: v1(3933.52,4117.26) 3981.63,4069.14 v1(3981.63,4000.14)
5V_REG: C37.2 C39.2 D5.2 LED9.1 R26.1 R29.1 U14.7 U14.8 | length 933.9
  Top Layer w10: C39.2 4024.16,3822.27 4006.47,3839.96 4006.47,3870.32 4012.91,3876.76 4044.27,3876.76 4062.67,3858.36 R29.1 4077.31,3840.5 4082.54,3840.5 4110.05,3812.98 C37.2 4171.56,3826.75 LED9.1 4166.65,3903.25 4166.65,3941.06 4102.36,4005.34 4102.36,4008.59 4087.93,4023.03 D5.2 ; U14.8 4027.83,3724.32 4055.68,3724.32 U14.7 ; v1(4237.61,3728.16) 4237.61,3719.75 R26.1
  Inner1 w10: v1(4161.63,3814.14) 4177.63,3814.14 4237.61,3754.16 v1(4237.61,3728.16)
5V_USB: D4.2 USBC2.A4 USBC2.A9 USBC2.B4 USBC2.B9 | length 705.8
  Top Layer w10: D4.2 4015.18,4068.03 4099.97,4152.83 4156.58,4152.83 4211.63,4097.77 4211.63,4055.32 4219.69,4047.26 ; USBC2.A9 4170.11,4047.26 4219.69,4047.26 ; USBC2.A4 4312.1,3905.29 4312.1,3987.68 4252.51,4047.26 4219.69,4047.26
$1N1788: R6.1 U2.41 | length 524.8
  Top Layer w10: R6.1 3297.63,4020.17 3307.63,4010.17 3348.14,4010.17 3413.63,3944.68 3413.63,3888.14 3458.85,3842.92 3458.85,3751.01 3533.34,3676.52 3533.34,3655.73 3533.65,3655.42 3533.65,3621.57 3536.55,3618.67 U2.41
$1N1792: D1.1 U2.46 | length 362.2
  Top Layer w10: v1(3618.62,3741.02) 3627.6,3732.04 3627.6,3659.9 3632.07,3655.42 3632.07,3621.86 U2.46
  Inner1 w10: v1(3618.62,3741.02) 3789.28,3741.02 3789.4,3740.9 3808.44,3740.9 3808.57,3741.02 3824.75,3741.02 v1(3843.63,3722.14)
$1N1793: C15.1 U2.49 | length 63.2
  Top Layer w10: U2.49 3802.94,3689.53 C15.1
$1N1794: R7.2 R9.1 U2.24 | length 241.7
  Top Layer w10: R7.2 3262.08,3778.59 3262.08,3834.16 U2.24@3274.93,3847.01 ; R9.1 3262.08,3889.69 3262.08,3859.87 U2.24@3274.93,3847.02 ; U2.24 U2.24@3274.93,3847.01
$1N1796: LED2.2 R6.2 | length 176.5
  Top Layer w10: R6.2 3297.63,4071.39 3402.38,4176.14 LED2.2
$1N1808: U2.5 X3.1 | length 139.2
  Top Layer w10: U2.5 3599.08,4058.85 3599.08,4092.42 3608.74,4102.09 3642.31,4102.09 3670.87,4130.64 X3.1
$1N1817: C14.1 U2.47 | length 567.4
  Top Layer w10: C14.1 3362.86,4019.23 3362.86,4018.91 3368.53,4013.24 3368.53,4009.6 3407.5,3970.63 3448.96,3970.63 3641.61,3777.98 3641.61,3666.16 3651.76,3656.01 3651.76,3621.85 U2.47
$1N1822: U2.6 X3.3 | length 88.5
  Top Layer w10: U2.6 3576.39,4055.85 X3.3
$1N1825: R8.2 SW1.1 SW1.2 U2.60 | length 550.6
  Top Layer w10: SW1.2 SW1.1 3684.17,4198.45 3751.32,4131.3 R8.2 3751.32,4066.26 3786.63,4030.94 3786.63,3996.92 3791.91,3991.64 3791.91,3918.92 3782.25,3909.25 3748.68,3909.25 U2.60
$1N1826: C13.1 U2.31 | length 87.2
  Top Layer w10: C13.1 3249.78,3684.06 3271.74,3706.02 3305.3,3706.02 U2.31
$1N1828: C12.2 U2.7 | length 79.4
  Top Layer w10: C12.2 3542,4102.09 3543.67,4102.09 3553.33,4092.42 3553.33,4090.75 3556.53,4087.56 U2.7
$1N3338: LED4.2 R4.2 | length 54.8
  Top Layer w10: R4.2 3781.76,4423.15 LED4.2
$1N4900: R34.1 USBC2.A5 | length 51.6
  Top Layer w10: R34.1 4245.59,3898.2 4245.59,3907.2 4264.92,3926.53 USBC2.A5
$1N5005: R33.2 USBC2.B5 | length 142
  Top Layer w10: R33.2 4090.58,4053.1 4149.02,3994.67 4162.06,3994.67 USBC2.B5
$1N5670: L1.1 U14.11 | length 460.6
  Top Layer w10: L1.1 3805.63,3522.63 3805.63,3559.8 3870.78,3624.95 3943.91,3624.95 3999.89,3568.97 4061.3,3568.97 4117.28,3624.95 U14.11
$1N5674: L1.2 U14.9 | length 110.8
  Top Layer w10: L1.2 4092.46,3655.12 U14.9
$1N5764: R24.1 U14.14 | length 74.2
  Top Layer w10: U14.14 4204.84,3602.98 R24.1
$1N6103: R26.2 U14.2 | length 70.1
  Top Layer w10: U14.2 4177.59,3688.49 4187.88,3698.78 4210.38,3698.78 R26.2
$1N6255: R28.2 R29.2 U14.5 | length 328.3
  Top Layer w10: R29.2 4040.55,3843.18 4040.55,3839.96 4054.03,3826.48 4076.73,3826.48 4145.58,3757.63 4146.73,3757.63 ; U14.5 4146.73,3757.63 ; R28.2 4227.19,3838.09 4146.73,3757.63
$1N6590: C38.1 U14.3 | length 190.8
  Top Layer w10: U14.3 4184,3728.08 4166.99,3745.1 4166.99,3754.2 4216.57,3803.78 4225.67,3803.78 4228.23,3801.23 C38.1
$1N6799: LED9.2 R31.2 | length 81.5
  Top Layer w10: R31.2 4103.42,3905.14 LED9.2
$1N9049: LED10.2 R32.2 | length 60.7
  Top Layer w10: LED10.2 3871.3,3981.15 R32.2
ADC_CURR: P1.3 U2.15 | length 936.8
  Top Layer w10: U2.15 3399.05,4018.73 3419.11,3998.66 3460.57,3998.66 3671.63,3787.6 3671.63,3713.17 v1(3686.96,3697.84) ; v1(3851.63,3566.14) 3851.63,3547.84 3915.2,3484.28 3915.2,3458.34 v1(3973.23,3400.31)
  Inner1 w10: v1(3686.96,3697.84) 3700.96,3697.84 3832.66,3566.14 v1(3851.63,3566.14)
GND: C1.1 C3.2 C4.2 C5.2 C6.2 C7.2 C8.1 C12.1 C13.2 C14.2 C24.1 C33.1 C34.2 C37.1 C38.2 C39.1 C40.1 C41.1 C44.2 C45.2 CN1.3 CN1.5 CN1.6 P1.2 P1.9 P1.10 R4.1 R7.1 R8.1 R28.1 R31.1 R32.1 R33.1 R34.2 U2.12 U2.18 U2.63 U12.2 U12.3 U12.6 U12.7 U12.9 U12.10 U12.11 U13.4 U13.9 U14.4 U14.6 U14.10 U14.15 U15.2 U15.5 U16.2 U16.5 U19.2 U19.5 U19.7 U19.8 USBC2.0 USBC2.1 USBC2.2 USBC2.3 USBC2.A1 USBC2.A12 USBC2.B1 USBC2.B12 X3.2 | length 2166.6
  Top Layer w10: U2.18 3344.65,3965.12 v1@3371.63,3938.14 ; v1(3523.63,4159.82) 3505.09,4141.28 3503.33,4141.28 3496.9,4134.84 3496.9,4133.09 3485.4,4121.6 v1(3468.87,4121.6) 3468.87,4100.01 3461.29,4092.42 3461.29,4058.86 U2.12 3461.29,4052.47 3461.29,4018.91 3470.95,4009.25 3504.51,4009.25 3547.62,3966.14 v1(3687.63,3966.14) 3688.65,3965.12 U2.63 ; U12.11 U12.10 U12.9 ; U12.3 U12.2 3942.57,3827.32 v1(3972.61,3797.28) ; U16.2 4007.83,3942.34 U16.5 4020.63,3946.06 4019.49,3944.92 4019.49,3933.85 4020.63,3932.72 4020.63,3911.14 v1(4025.63,3906.14) ; R33.1 4111.2,4087.18 USBC2.1 ; U14.6 4103.2,3709.38 4121.42,3691.16 ; U14.4 4121.42,3693.34 4121.42,3691.16 ; v1(4150.19,3663.2) 4122.23,3691.16 4121.42,3691.16
  Inner1 w10: v1(3195.71,3712.22) 3203.55,3712.22 v1(3259.55,3656.22) ; v1(3249.63,4011.83) 3285.63,4011.83 v1(3347.63,4073.83) 3414.93,4141.13 3439.15,4141.13 3458.69,4121.6 v1(3468.87,4121.6) 3369.73,4022.45 v1(3369.73,3936.24) ; v1(3495.08,3511.08) 3639.37,3366.8 v1(3695.36,3366.8) ; v1(3711.95,4117.16) 3757.55,4071.56 v1(3757.55,4022.22) ; v1(3766.47,3664.85) 3800.77,3699.15 3853.15,3699.15 3951.29,3797.28 v1(3972.61,3797.28)
  other v1: 3828.46,3240.97 3846.84,3323.4 4256.59,3467.83 4318.46,3487.97 4366.62,3568.25 4131.68,3581.11 4206.91,3634.34 4205.37,3751.88 4079.84,3780 3817.55,3825.15 4294.55,3829.06 4208.58,3862.19 4261.68,3866.09 4319.2,3876.2 3857.97,3877.02 3901.68,3960.9 3957,3961.21 4073.63,3996.14 3941.63,4008.14 4151.93,4063.32 3618.37,4161.4 3770.79,4322.29 3686.93,4427.34
GYRO_EXTI: U2.58 U12.4 | length 320.5
  Top Layer w10: v1(3696.02,3866.69) U2.58 ; U12.4 3921,3870.77 v1(3921,3887.16)
  Inner1 w10: v1(3696.02,3866.69) 3714.57,3848.14 3881.98,3848.14 v1(3921,3887.16)
MOTOR_1: P1.5 U2.27 | length 858
  Top Layer w10: U2.27 3311.69,3784.76 3345.25,3784.76 3357.87,3772.14 v1(3435.86,3772.14)
  Inner1 w10: v1(3435.86,3772.14) 3495.15,3772.14 3783.66,3483.64 4001.37,3483.64 v1(4029,3456)
MOTOR_2: P1.6 U2.26 | length 882.4
  Top Layer w10: U2.26 3311.68,3804.45 3345.25,3804.45 3346.57,3803.13 v1(3435.86,3803.13)
  Inner1 w10: v1(3435.86,3803.13) 3483.98,3803.13 3789.46,3497.65 4042.92,3497.65 v1(4056.74,3483.83)
MOTOR_3: P1.7 U2.17 | length 1014.4
  Top Layer w10: U2.17 3310.5,3986.81 3351.68,3986.81 3392.72,3945.77 3392.72,3876.27 v1(3435.86,3833.13)
  Inner1 w10: v1(3435.86,3833.13) 3473.8,3833.13 3795.27,3511.67 v1(4084.58,3511.67)
MOTOR_4: P1.8 U2.16 | length 1019.7
  Top Layer w10: U2.16 3382.55,4052.47 3382.55,4015.4 3413.31,3984.64 3454.77,3984.64 3655.63,3783.78 3655.63,3696.66 3687.01,3665.27 v1(3701.01,3665.27)
  Inner1 w10: v1(3701.01,3665.27) 3713.71,3665.27 3839.47,3539.51 v1(4112.51,3539.51)
RX1: P1.4 U2.43 | length 613.8
  Top Layer w10: v1(3556.33,3672.09) 3562.73,3672.09 3579.4,3655.42 3579.4,3621.86 U2.43
  Inner1 w10: v1(3556.33,3672.09) 3640.19,3588.24 3659.24,3588.24 3819.32,3428.15 v1(4001.07,3428.15)
RX3: U2.30 U19.4 | length 1111.7
  Top Layer w10: U2.30 3358.87,3728.9 v1(3365.63,3722.14) ; U19.4 4017.63,4315.64 v1(4017.63,4316.14)
  Inner1 w10: v1(3365.63,3722.14) 3368.16,3722.14 3382.64,3736.62 3382.64,3755.67 3398.85,3771.88 3398.85,3848.46 3557.6,4007.21 3557.6,4068.11 3805.63,4316.14 v1(4017.63,4316.14)
RX6: CN1.2 U2.38 | length 1029.1
  Top Layer w10: U2.38 3477.79,3666.85 v1(3494.14,3683.21) ; v1(3649.72,3565.24) 3649.82,3565.13 3743.94,3565.13 v1(3829.87,3651.07)
  Inner1 w10: v1(3494.14,3683.21) 3512.71,3683.21 3630.67,3565.24 v1(3649.72,3565.24) ; v1(3829.87,3651.07) 3830.73,3651.07 3881.81,3702.14 4244.11,3702.14 4260.6,3718.64 4260.6,3724.53 4281.4,3745.33 4317.61,3745.33 v1(4322.76,3740.18)
SPI_CS_1: U2.20
SPI_CS_2: R3.1 U2.33 U13.1 | length 625.3
  Top Layer w10: U2.33 3379.36,3515 3447.35,3447 3448.2,3447 3483.92,3411.28 ; R3.1 3483.92,3411.28 ; U13.1 3738.47,3219.63 3675.57,3219.63 3483.92,3411.28
SPI_CS_3: U2.55 U12.12 | length 111.4
  Top Layer w10: U2.55 3748.68,3804.45 3782.25,3804.45 3795.57,3791.14 3835.39,3791.14 3841.55,3797.3 U12.12
SPI_MISO_1: U2.22
SPI_MISO_2: U2.35 U13.2 | length 707.9
  Top Layer w10: U2.35 3418.73,3597.05 3421.92,3593.85 3421.92,3581.77 3445.46,3558.24 3579.76,3558.24 3639.07,3498.93 3658.42,3498.93 3678.18,3518.69 3711.08,3518.69 3830.54,3399.23 3830.54,3363.8 v1(3798.73,3331.99)
  Inner1 w10: v1(3776.13,3252.69) 3798.73,3275.29 v1(3798.73,3331.99)
SPI_MISO_3: U2.52 U12.1 | length 207.5
  Top Layer w10: U2.52 3748.68,3751.77 3782.25,3751.77 3794.37,3763.89 v1(3798.92,3763.89) ; v1(3885.13,3766.02) 3895.06,3766.02 3897.75,3768.71 3897.75,3773.8 3903.42,3779.47 3903.42,3794.13 U12.1
  Inner1 w10: v1(3798.92,3763.89) 3801.06,3766.02 v1(3885.13,3766.02)
SPI_MOSI_1: U2.23
SPI_MOSI_2: U2.36 U13.5 | length 256.8
  Top Layer w10: U2.36 3438.42,3585.1 3451.26,3572.25 3597.99,3572.25 U13.5@3639.27,3530.97
SPI_MOSI_3: U2.53 U12.14 | length 277.9
  Top Layer w10: v1(3702.02,3768.27) U2.53 ; v1(3883.64,3825.15) 3883.64,3815.24 3883.74,3815.14 3883.74,3800.49 U12.14
  Inner1 w10: v1(3702.02,3768.27) 3723.89,3790.14 3848.63,3790.14 v1(3883.64,3825.15)
SPI_SCK_1: U2.21
SPI_SCK_2: U2.34 U13.6 | length 275.7
  Top Layer w10: U2.34 3402.23,3615.48 3402.23,3581.64 3439.65,3544.22 3555.31,3544.22 U13.6@3603.91,3495.61
SPI_SCK_3: U2.51 U12.13 | length 158.7
  Top Layer w10: U2.51 3748.69,3732.09 3816.67,3732.09 3864.05,3779.47 3864.05,3794.11 U12.13
TX1: U2.42
TX3: U2.29 U19.3 | length 1120.6
  Top Layer w10: U2.29 3310.94,3746.14 v1(3405.63,3746.14) ; U19.3 4003.8,4244.31 v1(4047.63,4288.14)
  Inner1 w10: v1(3405.63,3746.14) 3405.63,3755.38 3412.86,3762.62 3412.86,3842.66 3571.61,4001.41 3571.61,4062.3 3802.44,4293.13 3847.15,4293.13 3852.15,4288.14 v1(4047.63,4288.14)
TX6: CN1.1 U2.37 | length 1039.4
  Top Layer w10: v1(3457.62,3681.21) 3456.69,3681.21 3454.91,3679.42 3454.91,3621.85 U2.37 ; v1(3670.91,3541.68) 3755,3541.68 v1(3831.87,3618.55)
  Inner1 w10: v1(3457.62,3681.21) 3463.62,3681.21 3602.58,3542.25 3670.35,3542.25 v1(3670.91,3541.68) ; v1(3831.87,3618.55) 3866.19,3652.88 3866.19,3666.71 3887.61,3688.13 4249.91,3688.13 4274.13,3712.34 v1(4294.92,3712.34)
USB_D+_PA12: R22.2 U2.45 | length 758.8
  Top Layer w10: v1(3603.66,3783.42) 3603.66,3769.28 3581.63,3747.25 3581.63,3699.13 3612.39,3668.37 3612.39,3621.96 U2.45
  Inner1 w10: v1(3603.66,3783.42) 3608.62,3788.38 3608.62,4057.13 3766.65,4215.16 v1(3838.33,4215.16)
USB_D-_PA11: R23.2 U2.44 | length 799.1
  Top Layer w10: v1(3573.66,3794.63) 3565.63,3786.61 3565.63,3695.31 3593.42,3667.53 3593.42,3621.15 U2.44
  Inner1 w10: v1(3573.66,3794.63) 3575.63,3796.61 3575.63,3985.6 3585.63,3995.6 3585.63,4056.5 3799.27,4270.14 v1(3837.63,4270.14)
USB_DN: R23.1 USBC2.A7 USBC2.B7 | length 592.5
  Top Layer w10: R23.1 3990.14,4157.71 v1(3990.14,4153.63) ; USBC2.A7 4227.11,3972.25 4246.45,3991.58 4255.55,3991.58 4270.34,3976.8 4270.34,3967.7 4251,3948.37 USBC2.B7
  Inner1 w10: v1(3990.14,4153.63) 4013.35,4153.63 4142.84,4024.14 4228.08,4024.14 v1(4253.63,3998.59)
USB_DP: R22.1 USBC2.A6 USBC2.B6 | length 548.9
  Top Layer w10: R22.1 3892.81,4215.16 v1(3960.14,4147.83) ; USBC2.B6 4209.24,3982.21 4189.91,3962.88 4189.91,3953.78 4204.69,3938.99 4213.79,3938.99 4233.13,3958.33 USBC2.A6
  Inner1 w10: v1(3960.14,4147.83) 4175.99,3931.98 v1(4207.63,3931.98)
VBAT: C44.1 C45.1 P1.1 R9.2 R24.2 U14.1 U14.12 U14.13 | length 2085.6
  Top Layer w10: U14.1@4187.64,3673.1 4200.67,3673.1 4227.15,3646.62 4239.37,3646.62 4241.64,3648.9 4250.74,3648.9 4298.47,3601.17 R24.2
  Top Layer w19.68: C45.1 3917.65,3330.16 P1.1 3998.16,3264.14 4069.63,3264.14 4191.63,3386.14 4191.63,3502.14 4223.47,3533.98 4223.47,3547.3 ; U14.12 4156.12,3600.79 4163.05,3607.72 ; U14.13@4163.05,3612.48 4163.05,3607.72 ; C44.1@4350.8,3520.32 4323.82,3547.3 R24.2 4223.47,3547.3 ; 4163.05,3607.72 4223.47,3547.3
  Inner1 w19.68: v1(3228.87,3940.9) 3242.87,3940.9 3337.8,3845.98 3337.8,3710.61 3643.09,3405.32 3854.46,3405.32 v1(3917.63,3342.14)
pads on no net: MH1.1 MH3.1 MH4.1 MH5.1 U2.2 U2.3 U2.4 U2.8 U2.9 U2.10 U2.11 U2.14 U2.25 U2.28 U2.39 U2.40 U2.50 U2.54 U2.56 U2.57 U2.59 U2.61 U2.62 U19.6 USBC2.A8 USBC2.B8

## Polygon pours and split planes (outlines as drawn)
GND on Top Layer (solid, remove dead copper, pour order 0): 3034,3839.17 3869.17,4674.33 4704.33,3839.17 3869.17,3004
GND on Inner1 (solid, remove dead copper): 3000,3835.17 3835.17,4670.33 4670.33,3835.17 3835.17,3000

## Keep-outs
Board Outline Layer:
  lines w10: 3157.27,3711.89 3741.89,3127.27 ccw(c3867.17,3252.55) 3992.44,3127.27 4577.06,3711.89 ccw(c4451.78,3837.16) 4577.06,3962.44 3992.44,4547.06 ccw(c3867.17,4421.78) 3741.89,4547.05 3157.27,3962.44 ccw(c3282.55,3837.16) 3157.27,3711.89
